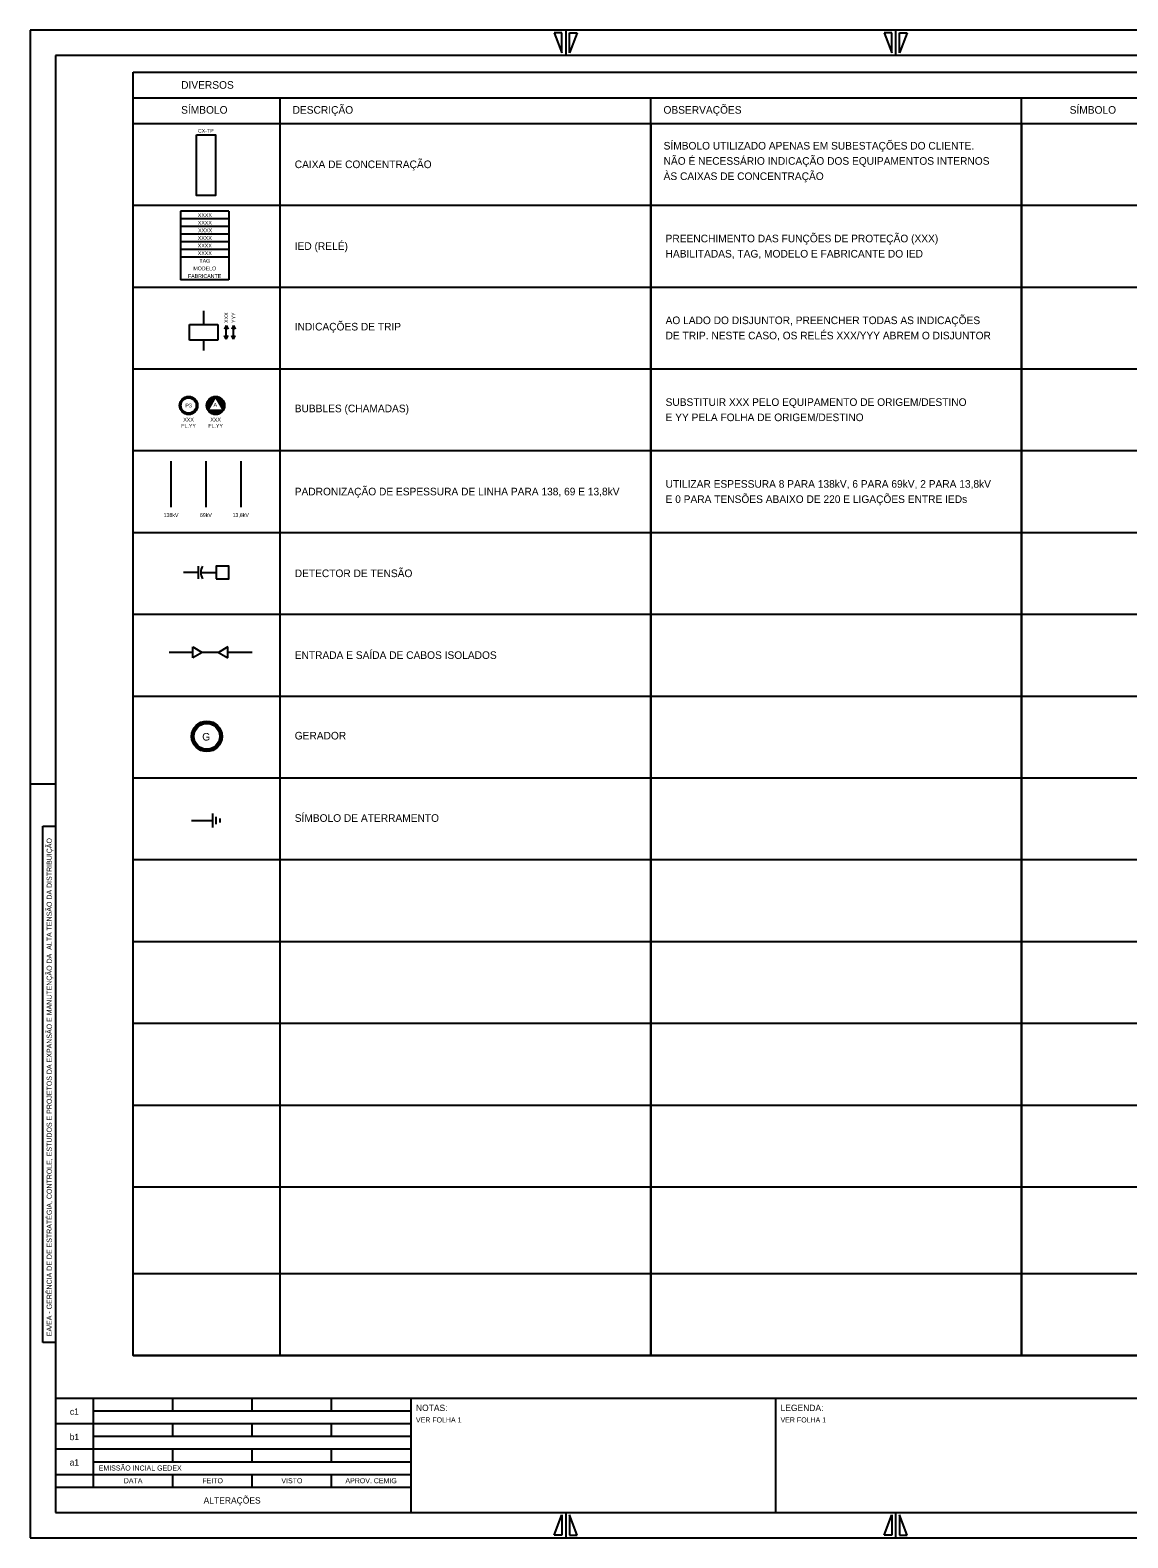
# Model space of a CAD drawing. Extents: x 563 to 3226, y 358 to 960.
# Drawn here: x 2385 to 2818, y 358 to 952 of the extents above; entities that cross this region are included whole.
import ezdxf

# ---------------------------------------------------------------- set-up
doc = ezdxf.new("R2010")
doc.units = 0
for name, color, linetype in [('COMENTÁRIOS_CEMIG_03-12-2019', 7, 'Continuous'), ('Default', 7, 'Continuous'), ('Level 1', 7, 'Continuous'), ('Level 2', 7, 'Continuous'), ('New Level (0)', 7, 'Continuous')]:
    doc.layers.add(name, color=color, linetype=linetype)

msp = doc.modelspace()

# ---------------------------------------------------------------- linework, layer by layer
for radius in [6, 5.7, 5.4, 5.1]:
    msp.add_circle((2454.8, 673.73), radius)
at = {"layer": 'COMENTÁRIOS_CEMIG_03-12-2019'}
for p, q in [((2454.69, 804.18), (2458.15, 807.64)), ((2454.69, 804.03), (2458.18, 807.53)), ((2454.69, 803.9), (2457.99, 807.19)), ((2454.7, 804.33), (2458, 807.63)), ((2454.7, 803.77), (2457.8, 806.86)), ((2454.71, 804.48), (2457.84, 807.61)), ((2454.72, 803.64), (2457.6, 806.52)), ((2454.73, 804.64), (2457.68, 807.59)), ((2454.73, 803.51), (2457.41, 806.19)), ((2454.76, 803.39), (2457.22, 805.85)), ((2454.77, 804.82), (2457.51, 807.56)), ((2454.78, 803.28), (2457.02, 805.52)), ((2454.81, 805), (2457.32, 807.51)), ((2454.81, 803.16), (2456.83, 805.19)), ((2454.84, 803.05), (2456.64, 804.85)), ((2454.87, 805.21), (2457.12, 807.45)), ((2454.87, 802.95), (2456.44, 804.52)), ((2454.91, 802.84), (2456.25, 804.18)), ((2454.95, 802.74), (2456.06, 803.85)), ((2454.96, 805.43), (2456.89, 807.37)), ((2454.99, 802.64), (2455.86, 803.51)), ((2455.04, 802.54), (2455.67, 803.18)), ((2455.08, 805.69), (2456.63, 807.25)), ((2455.08, 802.45), (2455.48, 802.84)), ((2455.13, 802.36), (2455.28, 802.51)), ((2455.17, 802.29), (2455.18, 802.3)), ((2455.23, 802.2), (2455.33, 802.3)), ((2455.27, 806.03), (2456.3, 807.06)), ((2455.28, 802.12), (2455.47, 802.3)), ((2455.34, 802.03), (2455.61, 802.3)), ((2455.4, 801.95), (2455.75, 802.3)), ((2455.46, 801.87), (2455.89, 802.3)), ((2455.52, 801.79), (2456.03, 802.3)), ((2455.59, 801.72), (2456.17, 802.3)), ((2455.66, 801.64), (2456.32, 802.3)), ((2455.73, 801.57), (2456.46, 802.3)), ((2455.8, 801.5), (2456.6, 802.3)), ((2455.87, 801.43), (2456.74, 802.3)), ((2455.95, 801.37), (2456.88, 802.3)), ((2456.02, 801.3), (2457.02, 802.3)), ((2456.1, 801.24), (2457.16, 802.3)), ((2456.18, 801.18), (2457.31, 802.3)), ((2456.27, 801.12), (2457.45, 802.3)), ((2456.35, 801.07), (2457.59, 802.3)), ((2456.44, 801.01), (2457.73, 802.3)), ((2456.53, 800.96), (2457.87, 802.3)), ((2456.62, 800.91), (2458.01, 802.3)), ((2456.72, 800.87), (2458.15, 802.3)), ((2456.82, 800.82), (2458.3, 802.3)), ((2456.92, 800.78), (2458.44, 802.3)), ((2457.02, 800.74), (2458.58, 802.3)), ((2457.12, 800.71), (2458.72, 802.3)), ((2457.23, 800.67), (2458.86, 802.3)), ((2457.34, 800.64), (2459, 802.3)), ((2457.45, 800.61), (2459.14, 802.3)), ((2457.57, 800.59), (2459.29, 802.3)), ((2457.69, 800.57), (2459.43, 802.3)), ((2457.82, 800.55), (2459.57, 802.3)), ((2457.94, 800.54), (2459.71, 802.3)), ((2458.08, 800.53), (2459.85, 802.3)), ((2458.21, 800.52), (2459.99, 802.3)), ((2458.26, 807.6), (2458.3, 807.64)), ((2458.32, 807.51), (2458.43, 807.63)), ((2458.36, 800.53), (2460.13, 802.3)), ((2458.37, 807.43), (2458.57, 807.62)), ((2458.42, 807.34), (2458.69, 807.61)), ((2458.47, 807.25), (2458.82, 807.59)), ((2458.51, 800.53), (2460.28, 802.3)), ((2458.52, 807.16), (2458.94, 807.57)), ((2458.57, 807.07), (2459.05, 807.54)), ((2458.63, 806.98), (2459.17, 807.52)), ((2458.66, 800.55), (2460.42, 802.3)), ((2458.68, 806.89), (2459.28, 807.48)), ((2458.73, 806.8), (2459.38, 807.45)), ((2458.78, 806.71), (2459.49, 807.41)), ((2458.83, 806.62), (2459.59, 807.37)), ((2458.83, 800.57), (2460.56, 802.3)), ((2458.89, 806.53), (2459.69, 807.33)), ((2458.94, 806.44), (2459.79, 807.29)), ((2458.99, 806.35), (2459.88, 807.24)), ((2459, 800.61), (2460.7, 802.3)), ((2459.04, 806.26), (2459.97, 807.19)), ((2459.09, 806.17), (2460.06, 807.14)), ((2459.14, 806.08), (2460.15, 807.08)), ((2459.19, 800.65), (2460.84, 802.3)), ((2459.2, 805.99), (2460.23, 807.03)), ((2459.25, 805.9), (2460.32, 806.97)), ((2459.3, 805.81), (2460.4, 806.91)), ((2459.35, 805.72), (2460.48, 806.85)), ((2459.4, 805.63), (2460.56, 806.78)), ((2459.4, 800.71), (2460.98, 802.3)), ((2459.45, 805.54), (2460.63, 806.72)), ((2459.51, 805.45), (2460.7, 806.65)), ((2459.56, 805.36), (2460.78, 806.58)), ((2459.61, 805.27), (2460.84, 806.51)), ((2459.62, 800.8), (2461.12, 802.3)), ((2459.66, 805.18), (2460.91, 806.43)), ((2459.71, 805.09), (2460.98, 806.36)), ((2459.77, 805), (2461.04, 806.28)), ((2459.82, 804.91), (2461.1, 806.2)), ((2459.87, 804.83), (2461.16, 806.12)), ((2459.89, 800.93), (2461.27, 802.3)), ((2459.92, 804.74), (2461.22, 806.03)), ((2459.97, 804.65), (2461.27, 805.95)), ((2460.02, 804.56), (2461.33, 805.86)), ((2460.08, 804.47), (2461.38, 805.77)), ((2460.13, 804.38), (2461.43, 805.67)), ((2460.18, 804.29), (2461.47, 805.58)), ((2460.23, 804.2), (2461.51, 805.48)), ((2460.24, 801.14), (2461.19, 802.08)), ((2460.28, 804.11), (2461.56, 805.38)), ((2460.33, 804.02), (2461.59, 805.28)), ((2460.39, 803.93), (2461.63, 805.17)), ((2460.44, 803.84), (2461.66, 805.06)), ((2460.49, 803.75), (2461.69, 804.95)), ((2460.54, 803.66), (2461.72, 804.84)), ((2460.59, 803.57), (2461.74, 804.72)), ((2460.65, 803.48), (2461.76, 804.6)), ((2460.7, 803.39), (2461.78, 804.47)), ((2460.75, 803.3), (2461.79, 804.34)), ((2460.8, 803.21), (2461.8, 804.21)), ((2460.85, 803.12), (2461.8, 804.07)), ((2460.9, 803.03), (2461.8, 803.93)), ((2460.96, 802.94), (2461.79, 803.78)), ((2461.01, 802.85), (2461.77, 803.62)), ((2461.06, 802.76), (2461.75, 803.45)), ((2461.11, 802.67), (2461.71, 803.27)), ((2461.16, 802.58), (2461.66, 803.08)), ((2461.21, 802.49), (2461.59, 802.87)), ((2461.27, 802.4), (2461.49, 802.63)), ((2461.32, 802.31), (2461.35, 802.35))]:
    msp.add_line(p, q, dxfattribs=at)
at = {"layer": 'Default'}
for p, q in [((2444.48, 880.58), (2444.48, 853.58)), ((2463.46, 880.58), (2444.48, 880.58)), ((2463.46, 880.58), (2463.46, 853.58)), ((2463.46, 877.58), (2444.48, 877.58)), ((2463.46, 877.58), (2444.48, 877.58)), ((2463.46, 874.58), (2444.48, 874.58)), ((2463.46, 871.58), (2444.48, 871.58)), ((2463.46, 868.58), (2444.48, 868.58)), ((2463.46, 868.58), (2444.48, 868.58)), ((2463.46, 865.58), (2444.48, 865.58)), ((2463.46, 862.58), (2444.48, 862.58)), ((2463.46, 853.58), (2444.48, 853.58)), ((2453.55, 841.31), (2453.55, 836)), ((2447.93, 829.88), (2447.93, 836)), ((2447.93, 836), (2459.17, 836)), ((2459.17, 836), (2459.17, 829.88)), ((2462.44, 835.62), (2461.74, 834.21)), ((2462.44, 830.26), (2461.74, 831.67)), ((2462.44, 830.26), (2462.44, 835.62)), ((2462.44, 835.62), (2463.15, 834.21)), ((2462.44, 830.26), (2463.15, 831.67)), ((2465.29, 835.62), (2464.59, 834.21)), ((2465.29, 830.26), (2464.59, 831.67)), ((2465.29, 830.26), (2465.29, 835.62)), ((2465.29, 835.62), (2466, 834.21)), ((2465.29, 830.26), (2466, 831.67)), ((2459.17, 829.88), (2447.93, 829.88)), ((2453.55, 829.88), (2453.55, 825.78)), ((2458.25, 807.64), (2455.17, 802.3)), ((2455.17, 802.3), (2461.33, 802.3)), ((2461.33, 802.3), (2458.25, 807.64)), ((2451.54, 738.32), (2445.54, 738.32)), ((2451.54, 735.82), (2451.54, 740.82)), ((2452.42, 738.32), (2458.42, 738.32)), ((2457.09, 643.37), (2457.09, 637.79)), ((2458.49, 639.18), (2458.49, 641.98)), ((2448.71, 640.58), (2457.09, 640.58)), ((2459.97, 641.36), (2459.97, 639.8))]:
    msp.add_line(p, q, dxfattribs=at)
msp.add_lwpolyline([(2458.42, 735.82), (2463.42, 735.82), (2463.42, 740.82), (2458.42, 740.82)], close=True, dxfattribs=at)
for centre, radius in [((2447.62, 804.08), 3.56), ((2447.62, 804.08), 3.38), ((2447.62, 804.08), 3.2), ((2447.62, 804.08), 3.02), ((2458.25, 804.08), 3.56)]:
    msp.add_circle(centre, radius, dxfattribs=at)
msp.add_arc((2457.42, 738.32), 5, 150, 210, dxfattribs=at)
at = {"layer": 'Level 1'}
for p, q in [((2449.27, 704.61), (2449.27, 708.94)), ((2449.27, 708.94), (2453.02, 706.77)), ((2463.13, 708.94), (2459.38, 706.77)), ((2463.13, 704.61), (2463.13, 708.94)), ((2453.02, 706.77), (2449.27, 704.61)), ((2459.38, 706.77), (2463.13, 704.61))]:
    msp.add_line(p, q, dxfattribs=at)
at = {"layer": 'Level 2'}
for p, q in [((2449.27, 706.77), (2439.98, 706.77)), ((2459.38, 706.77), (2453.02, 706.77)), ((2472.66, 706.77), (2463.13, 706.77))]:
    msp.add_line(p, q, dxfattribs=at)
at = {"layer": 'New Level (0)'}
for p, q in [((2385.19, 951.96), (2385.19, 357.96)), ((3226.19, 951.96), (2385.19, 951.96)), ((3226.19, 951.96), (2385.19, 951.96)), ((2385.19, 951.96), (2385.19, 357.96)), ((2594.69, 950.96), (2591.69, 950.96)), ((2591.69, 950.96), (2594.69, 942.96)), ((2594.69, 942.96), (2594.69, 950.96)), ((2596.19, 951.96), (2596.19, 941.96)), ((2597.69, 942.96), (2597.69, 950.96)), ((2597.69, 950.96), (2600.69, 950.96)), ((2600.69, 950.96), (2597.69, 942.96)), ((2724.69, 950.96), (2721.69, 950.96)), ((2721.69, 950.96), (2724.69, 942.96)), ((2724.69, 942.96), (2724.69, 950.96)), ((2726.19, 951.96), (2726.19, 941.96)), ((2727.69, 942.96), (2727.69, 950.96)), ((2727.69, 950.96), (2730.69, 950.96)), ((2730.69, 950.96), (2727.69, 942.96)), ((2395.19, 941.96), (2395.19, 367.96)), ((3216.19, 941.96), (2395.19, 941.96)), ((2395.19, 941.96), (2395.19, 367.96)), ((2425.75, 915.21), (2425.75, 935.35)), ((2425.75, 935.35), (3125.92, 935.35)), ((2425.75, 925.28), (2797.42, 925.28)), ((2483.59, 925.28), (2483.59, 429.83)), ((2629.71, 915.21), (2629.71, 925.28)), ((2775.83, 915.21), (2775.83, 925.28)), ((2775.83, 923.47), (2775.83, 925.28)), ((2775.83, 925.28), (3125.92, 925.28)), ((2775.83, 915.21), (2775.83, 923.47)), ((2425.75, 882.98), (3125.92, 882.98)), ((2425.75, 850.75), (3125.92, 850.75)), ((2425.75, 818.53), (3125.92, 818.53)), ((2425.75, 786.3), (3125.92, 786.3)), ((2440.67, 782.09), (2440.67, 764.05)), ((2454.4, 782.09), (2454.4, 764.05)), ((2468.14, 782.09), (2468.14, 764.05)), ((2425.75, 754.07), (3125.92, 754.07)), ((2425.75, 721.84), (3125.92, 721.84)), ((2425.75, 689.61), (3125.92, 689.61)), ((2385.19, 654.96), (2395.19, 654.96)), ((2425.75, 657.39), (3125.92, 657.39)), ((2390.19, 638.29), (2395.19, 638.29)), ((2390.19, 434.97), (2390.19, 638.29)), ((2425.75, 625.16), (3125.92, 625.16)), ((2425.75, 592.93), (3125.92, 592.93)), ((2425.75, 560.7), (3125.92, 560.7)), ((2425.75, 528.47), (3125.92, 528.47)), ((2425.75, 528.47), (3125.92, 528.47)), ((2425.75, 496.25), (3125.92, 496.25)), ((2425.75, 462.06), (3125.92, 462.06)), ((2395.19, 434.97), (2390.19, 434.97)), ((2425.75, 429.83), (3125.92, 429.83)), ((2395.19, 412.96), (3216.19, 412.96)), ((2410.19, 377.96), (2410.19, 412.96)), ((2441.44, 407.96), (2441.44, 412.96)), ((2472.69, 407.96), (2472.69, 412.96)), ((2503.94, 407.96), (2503.94, 412.96)), ((2535.19, 412.96), (2535.19, 367.96)), ((2678.85, 412.96), (2678.85, 367.96)), ((2410.19, 407.96), (2535.19, 407.96)), ((2395.19, 402.96), (2535.19, 402.96)), ((2441.44, 397.96), (2441.44, 402.96)), ((2472.69, 397.96), (2472.69, 402.96)), ((2503.94, 397.96), (2503.94, 402.96)), ((2395.19, 392.96), (2535.19, 392.96)), ((2410.19, 397.96), (2535.19, 397.96)), ((2441.44, 387.96), (2441.44, 392.96)), ((2472.69, 387.96), (2472.69, 392.96)), ((2503.94, 387.96), (2503.94, 392.96)), ((2410.19, 387.96), (2535.19, 387.96)), ((2395.19, 382.96), (2535.19, 382.96)), ((2441.44, 377.96), (2441.44, 382.96)), ((2472.69, 377.96), (2472.69, 382.96)), ((2503.94, 377.96), (2503.94, 382.96)), ((2395.19, 377.96), (2535.19, 377.96)), ((2395.19, 367.96), (3216.19, 367.96)), ((2395.19, 367.96), (3216.19, 367.96)), ((2591.69, 358.96), (2594.69, 366.96)), ((2594.69, 366.96), (2594.69, 358.96)), ((2596.19, 367.96), (2596.19, 357.96)), ((2597.69, 366.96), (2597.69, 358.96)), ((2600.69, 358.96), (2597.69, 366.96)), ((2721.69, 358.96), (2724.69, 366.96)), ((2724.69, 366.96), (2724.69, 358.96)), ((2726.19, 367.96), (2726.19, 357.96)), ((2727.69, 366.96), (2727.69, 358.96)), ((2730.69, 358.96), (2727.69, 366.96)), ((2385.19, 357.96), (3226.19, 357.96)), ((2385.19, 357.96), (3226.19, 357.96)), ((2594.69, 358.96), (2591.69, 358.96)), ((2597.69, 358.96), (2600.69, 358.96)), ((2724.69, 358.96), (2721.69, 358.96)), ((2727.69, 358.96), (2730.69, 358.96))]:
    msp.add_line(p, q, dxfattribs=at)
for points in [[(2425.75, 915.21), (2629.71, 915.21), (2629.71, 429.83), (2425.75, 429.83)], [(2629.71, 915.21), (2775.83, 915.21), (2775.83, 429.83), (2629.71, 429.83)], [(2775.83, 915.21), (2979.79, 915.21), (2979.79, 429.83), (2775.83, 429.83)], [(2450.68, 910.68), (2458.16, 910.68), (2458.16, 886.85), (2450.68, 886.85)]]:
    msp.add_lwpolyline(points, close=True, dxfattribs=at)

# ---------------------------------------------------------------- texts
at = {"layer": 'Default'}
for s, height, p in [('DIVERSOS', 3, (2444.68, 928.87)), ('SÍMBOLO', 3, (2444.68, 919.04)), ('DESCRIÇÃO', 3, (2488.6, 919.04)), ('OBSERVAÇÕES', 3, (2634.72, 919.04)), ('SÍMBOLO', 3, (2794.76, 919.04)), ('CX-TP', 1.5, (2451.29, 911.56)), ('SÍMBOLO UTILIZADO APENAS EM SUBESTAÇÕES DO CLIENTE.', 3, (2634.77, 904.92)), ('CAIXA DE CONCENTRAÇÃO', 3, (2489.43, 897.6)), ('NÃO É NECESSÁRIO INDICAÇÃO DOS EQUIPAMENTOS INTERNOS ', 3, (2634.77, 898.92)), ('ÀS CAIXAS DE CONCENTRAÇÃO', 3, (2634.77, 892.92)), ('XXXX', 1.5, (2451.26, 878.33)), ('XXXX', 1.5, (2451.26, 875.33)), ('XXXX', 1.5, (2451.37, 872.33)), ('XXXX', 1.5, (2451.23, 869.33)), ('XXXX', 1.5, (2451.23, 866.33)), ('IED (RELÉ)', 3, (2489.43, 865.37)), ('PREENCHIMENTO DAS FUNÇÕES DE PROTEÇÃO (XXX) ', 3, (2635.55, 868.37)), ('XXXX', 1.5, (2451.23, 863.33)), ('TAG', 1.5, (2451.87, 860.33)), ('HABILITADAS, TAG, MODELO E FABRICANTE DO IED', 3, (2635.55, 862.37)), ('FABRICANTE', 1.5, (2447.35, 854.33)), ('MODELO', 1.5, (2449.48, 857.33)), ('AO LADO DO DISJUNTOR, PREENCHER TODAS AS INDICAÇÕES', 3, (2635.55, 836.14)), ('INDICAÇÕES DE TRIP', 3, (2489.43, 833.64)), ('DE TRIP. NESTE CASO, OS RELÉS XXX/YYY ABREM O DISJUNTOR', 3, (2635.55, 830.14)), ('P3', 1.5, (2446.34, 803.33)), ('A', 1.5, (2457.42, 803.61)), ('BUBBLES (CHAMADAS)', 3, (2489.43, 801.41)), ('SUBSTITUIR XXX PELO EQUIPAMENTO DE ORIGEM/DESTINO', 3, (2635.55, 803.91)), ('FL.YY', 1.5, (2444.71, 795.35)), ('XXX', 1.5, (2445.53, 797.74)), ('FL.YY', 1.5, (2455.38, 795.35)), ('XXX', 1.5, (2456.2, 797.74)), ('E YY PELA FOLHA DE ORIGEM/DESTINO', 3, (2635.55, 797.91)), ('PADRONIZAÇÃO DE ESPESSURA DE LINHA PARA 138, 69 E 13,8kV', 3, (2489.43, 768.68)), ('UTILIZAR ESPESSURA 8 PARA 138kV, 6 PARA 69kV, 2 PARA 13,8kV', 3, (2635.55, 771.68)), ('E 0 PARA TENSÕES ABAIXO DE 220 E LIGAÇÕES ENTRE IEDs', 3, (2635.55, 765.68)), ('138kV', 1.5, (2437.75, 760.16)), ('69kV', 1.5, (2452.06, 760.16)), ('13,8kV', 1.5, (2464.92, 760.16)), ('DETECTOR DE TENSÃO', 3, (2489.43, 736.46)), ('ENTRADA E SAÍDA DE CABOS ISOLADOS', 3, (2489.43, 704.23)), ('G', 3, (2452.99, 672.07)), ('GERADOR', 3, (2489.43, 672.5)), ('SÍMBOLO DE ATERRAMENTO', 3, (2489.43, 640.05))]:
    msp.add_text(s, height=height, dxfattribs=at).set_placement(p)
for s, p in [('XXX', (2463.2, 836.62)), ('YYY', (2466.05, 836.62))]:
    msp.add_text(s, height=1.5, rotation=90, dxfattribs=at).set_placement(p)
at = {"layer": 'New Level (0)'}
msp.add_text('EA/EA - GERÊNCIA DE DE ESTRATÉGIA, CONTROLE, ESTUDOS E PROJETOS DA EXPANSÃO E MANUTENÇÃO DA  ALTA TENSÃO DA DISTRIBUIÇÃO', height=2, rotation=90, dxfattribs=at).set_placement((2393.69, 437.39))
for s, height, p in [('NOTAS:', 2.5, (2537.19, 407.91)), ('LEGENDA:', 2.5, (2680.85, 407.91)), ('c1', 2.5, (2400.84, 406.44)), ('VER FOLHA 1', 2, (2537.19, 403.41)), ('VER FOLHA 1', 2, (2680.85, 403.41)), ('b1', 2.5, (2400.74, 396.44)), ('a1', 2.5, (2400.74, 386.44)), ('EMISSÃO INCIAL GEDEX', 2, (2412.19, 384.46)), ('DATA', 2, (2422.08, 379.46)), ('FEITO', 2, (2453.01, 379.46)), ('VISTO', 2, (2484.18, 379.46)), ('APROV. CEMIG', 2, (2509.4, 379.46)), ('ALTERAÇÕES', 2.5, (2453.53, 371.46))]:
    msp.add_text(s, height=height, dxfattribs=at).set_placement(p)

doc.saveas('drawing.dxf')
